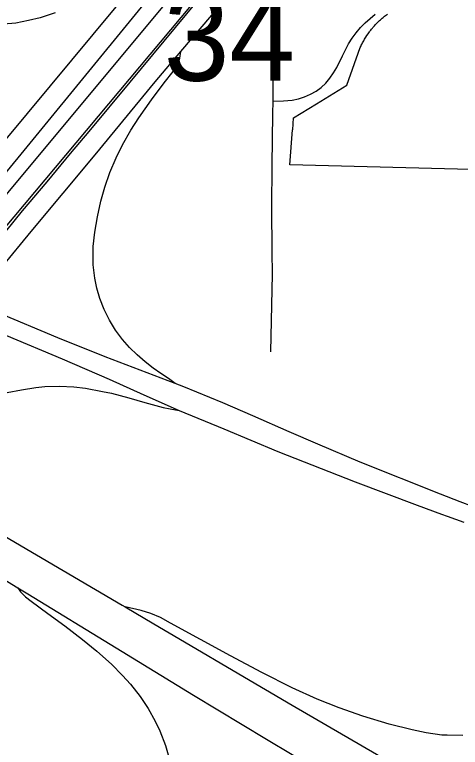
# Model space of a CAD drawing. Extents: x 0 to 34, y 0 to 22.
# Drawn here: x 5.8803 to 6.0913, y 18.0367 to 18.3832 of the extents above; entities that cross this region are included whole.
import ezdxf

# ---------------------------------------------------------------- set-up
doc = ezdxf.new("R2010")
doc.units = 0
for name, color, linetype in [('GM_X_Corporation', 7, 'Continuous'), ('GM_X_Interchange_Ramps', 7, 'Continuous'), ('GM_X_Interstate_Route', 7, 'Continuous'), ('GM_X_Section_Text', 7, 'Continuous'), ('GM_X_Township_Road', 7, 'Continuous'), ('SH_Text', 7, 'Continuous')]:
    doc.layers.add(name, color=color, linetype=linetype)

msp = doc.modelspace()

# ---------------------------------------------------------------- linework, layer by layer
at = {"layer": 'GM_X_Corporation'}
for points in [[(5.99893, 18.4296), (5.78524, 18.17482), (5.54192, 17.88304), (5.48185, 17.80886), (5.23248, 17.50716), (5.22686, 17.3672), (5.22496, 16.95635), (5.22215, 16.70979), (5.22146, 16.56588), (5.21817, 16.55274), (5.37026, 16.47), (5.47076, 16.41368), (5.47403, 16.41182), (5.61911, 16.32752), (5.62516, 16.32291), (5.6296, 16.31864), (5.63403, 16.31234), (5.7366, 16.25444)], [(6.18737, 18.30768), (6.01057, 18.31218), (6.01186, 18.32881), (6.01195, 18.32881), (6.01228, 18.33436), (6.02321, 18.3411), (6.03749, 18.34986), (6.0439, 18.36771), (6.04415, 18.36821), (6.04426, 18.36847), (6.04438, 18.36872), (6.04472, 18.3694), (6.04496, 18.3699), (6.04523, 18.37039), (6.0455, 18.37089), (6.04597, 18.37169), (6.04626, 18.37217), (6.04655, 18.37264), (6.04706, 18.37343), (6.04759, 18.3742), (6.04794, 18.37465), (6.04825, 18.3751), (6.04849, 18.37541), (6.04883, 18.37585), (6.04917, 18.37628), (6.04965, 18.37686), (6.04991, 18.37715), (6.05026, 18.37757), (6.05063, 18.378), (6.05099, 18.37842), (6.05137, 18.37881), (6.05178, 18.37922), (6.05217, 18.37962), (6.05258, 18.38), (6.05299, 18.38038), (6.0534, 18.38077), (6.05383, 18.38114), (6.05424, 18.3815), (6.05467, 18.38186), (6.05511, 18.38222), (6.05541, 18.38246), (6.05585, 18.38278), (6.05631, 18.38313), (6.05676, 18.38346)]]:
    msp.add_lwpolyline(points, dxfattribs=at)
at = {"layer": 'GM_X_Interchange_Ramps'}
for points in [[(5.95893, 18.36571), (5.99185, 18.40454), (6.0026, 18.41747), (6.11924, 18.56251), (6.15043, 18.60282), (6.16284, 18.61886), (6.17215, 18.63205), (6.17346, 18.63437), (6.17434, 18.63649), (6.1749, 18.63821), (6.17562, 18.64109)], [(5.95922, 18.42448), (5.85496, 18.29905), (5.83605, 18.27645)], [(5.8994, 18.38408), (5.89231, 18.38175), (5.88689, 18.38041), (5.88077, 18.37926), (5.87086, 18.37845)], [(5.73305, 18.09361), (5.73374, 18.09442), (5.76396, 18.13075), (5.78455, 18.15568), (5.79304, 18.16598), (5.8036, 18.1788), (5.81619, 18.19408), (5.84522, 18.22898), (5.85456, 18.24023), (5.86042, 18.2473), (5.88812, 18.28065), (5.91833, 18.31698), (5.94687, 18.35147), (5.95893, 18.36571)], [(5.95622, 18.20876), (5.95304, 18.2112), (5.94951, 18.21347), (5.9458, 18.21608), (5.94202, 18.21906), (5.93824, 18.22229), (5.93469, 18.22577), (5.93141, 18.22951), (5.92808, 18.23401), (5.92516, 18.23879), (5.9227, 18.24381), (5.92066, 18.24902), (5.91925, 18.25379), (5.9182, 18.25865), (5.91748, 18.26481), (5.91738, 18.26792), (5.91751, 18.27351), (5.91823, 18.28031), (5.91948, 18.28766), (5.92111, 18.29495), (5.92294, 18.30154), (5.92537, 18.30858), (5.92827, 18.31546), (5.93128, 18.3216), (5.93528, 18.32862), (5.939, 18.33435), (5.94513, 18.34296), (5.95112, 18.3509), (5.9553, 18.35631), (5.95698, 18.35868), (5.95795, 18.36062), (5.95844, 18.36256), (5.95893, 18.36571)], [(5.95622, 18.20876), (5.94295, 18.21379), (5.92319, 18.22132), (5.90066, 18.23032), (5.87196, 18.24229)], [(5.87635, 18.23143), (5.90277, 18.22044), (5.925, 18.21073), (5.9414, 18.20344), (5.95808, 18.19606)], [(6.08189, 18.15647), (6.04386, 18.17153), (6.02387, 18.18005), (6.01017, 18.18589), (5.99308, 18.19346), (5.97883, 18.19967), (5.9604, 18.20718), (5.95622, 18.20876)], [(5.8768, 18.20444), (5.88351, 18.20583), (5.89026, 18.20688), (5.8946, 18.20728), (5.90144, 18.20746), (5.90828, 18.20716), (5.91385, 18.20652), (5.92181, 18.20505), (5.92606, 18.20411), (5.93427, 18.20193), (5.94193, 18.19974), (5.95061, 18.19747), (5.9539, 18.19671), (5.95808, 18.19606)], [(5.95808, 18.19606), (5.97932, 18.18735), (6.00484, 18.1766), (6.04144, 18.16223), (6.07078, 18.15118), (6.08232, 18.14698), (6.08497, 18.14602)], [(6.09694, 18.15051), (6.09116, 18.1528), (6.08189, 18.15647)], [(6.08497, 18.14602), (6.09292, 18.14313)], [(5.88179, 18.11216), (5.88308, 18.11022), (5.88539, 18.10791), (5.88809, 18.10573), (5.89603, 18.10002), (5.90404, 18.09411), (5.91238, 18.08762), (5.91914, 18.08213), (5.92612, 18.07596), (5.93141, 18.07069), (5.93514, 18.06652), (5.93974, 18.06066), (5.94353, 18.05497), (5.94687, 18.04901), (5.94901, 18.04452), (5.95175, 18.03758), (5.95393, 18.02981)], [(6.09241, 18.04225), (6.08499, 18.04235), (6.08249, 18.04249), (6.07511, 18.0436), (6.06843, 18.04492), (6.05757, 18.04763), (6.04506, 18.05136), (6.03394, 18.0553), (6.02355, 18.05943), (6.01163, 18.06475), (5.99722, 18.07202), (5.98245, 18.07999), (5.95403, 18.09535), (5.94932, 18.09804), (5.94481, 18.1), (5.94011, 18.10137), (5.93261, 18.10312)]]:
    msp.add_lwpolyline(points, dxfattribs=at)
at = {"layer": 'GM_X_Interstate_Route'}
for points in [[(5.69101, 18.08612), (5.72912, 18.13206), (5.76151, 18.17063), (5.76924, 18.17995), (5.77999, 18.19292), (5.80598, 18.22425), (5.82808, 18.25073), (5.83458, 18.25851), (5.83706, 18.26148), (5.86961, 18.30074), (6.00233, 18.4626)], [(5.77029, 18.15271), (5.78514, 18.17062), (5.78784, 18.17387), (5.79578, 18.18347), (5.80013, 18.18872), (5.80725, 18.19735), (5.81709, 18.20937), (5.83771, 18.23428), (5.84563, 18.24384), (5.85166, 18.2511), (5.86469, 18.26682), (5.88404, 18.29035), (5.89561, 18.30418), (5.90679, 18.31753), (5.9156, 18.32798), (5.93493, 18.35125), (5.99932, 18.42898)], [(5.45017, 18.38473), (5.50003, 18.35547), (5.54105, 18.332), (5.59647, 18.29992), (5.64972, 18.26906), (5.70396, 18.23742), (5.73834, 18.2174), (5.762, 18.2037), (5.77062, 18.19854), (5.77999, 18.19292), (5.79026, 18.18677), (5.79578, 18.18347), (5.8036, 18.1788), (5.81876, 18.16973), (5.82388, 18.16667), (5.84053, 18.15697), (5.85502, 18.14851), (5.86254, 18.14412), (5.93122, 18.10394), (5.93261, 18.10312)], [(5.78339, 18.17165), (5.78514, 18.17062), (5.79304, 18.16598), (5.80199, 18.16071), (5.80525, 18.15873), (5.84186, 18.1365), (5.88179, 18.11216)], [(5.88179, 18.11216), (5.88645, 18.10932), (5.92836, 18.08369), (5.96495, 18.0613), (5.99957, 18.04047), (6.0359, 18.01885), (6.04114, 18.0158)], [(5.93261, 18.10312), (5.94624, 18.09515), (5.96071, 18.08665), (5.98642, 18.07149), (6.01161, 18.05669), (6.09937, 18.00577), (6.10408, 18.00304), (6.11374, 17.99743), (6.12386, 17.99065), (6.13959, 17.9801), (6.15799, 17.9674), (6.17464, 17.95542), (6.18565, 17.94732), (6.21647, 17.92418), (6.24593, 17.90172)]]:
    msp.add_lwpolyline(points, dxfattribs=at)
at = {"layer": 'GM_X_Township_Road'}
msp.add_line((6.00162, 18.22373), (6.00227, 18.26046), dxfattribs=at)
for points in [[(6.00263, 18.34231), (6.00271, 18.38769), (6.00276, 18.39653), (6.0026, 18.41747), (6.00254, 18.43287), (6.00249, 18.44064), (6.00233, 18.4626), (6.00229, 18.46771), (6.00228, 18.4765), (6.00228, 18.48684), (6.00205, 18.5084), (6.00204, 18.50941)], [(6.00263, 18.34231), (6.00759, 18.34241), (6.0117, 18.34278), (6.01467, 18.34347), (6.01756, 18.34439), (6.02032, 18.34557), (6.02294, 18.34703), (6.02535, 18.3488), (6.02752, 18.35085), (6.02945, 18.35314), (6.03118, 18.35563), (6.03272, 18.35826), (6.03549, 18.36379), (6.03832, 18.36939), (6.04, 18.37209), (6.04188, 18.37466), (6.04393, 18.37708), (6.04616, 18.37935), (6.04854, 18.38145), (6.05101, 18.3834)], [(6.00227, 18.26046), (6.0022, 18.27126), (6.002, 18.29184), (6.00225, 18.31203), (6.00257, 18.33633), (6.00263, 18.34231)]]:
    msp.add_lwpolyline(points, dxfattribs=at)
at = {"layer": 'SH_Text'}
msp.add_lwpolyline([(3.99293, 16.05737), (4.3255, 16.52675), (4.57529, 16.84083), (4.85248, 17.10757), (5.01711, 17.27058), (5.11699, 17.38197), (5.24033, 17.52767), (5.4467, 17.77753), (5.74271, 18.13817), (6.17725, 18.65894), (6.37399, 18.89616), (6.60804, 19.17492), (6.883, 19.50486), (7.02018, 19.66742)], dxfattribs=at)

# ---------------------------------------------------------------- texts
at = {"layer": 'GM_X_Section_Text'}
msp.add_text('34', height=0.041856, rotation=0, dxfattribs=at).set_placement((5.95082, 18.35196))

doc.saveas('drawing.dxf')
